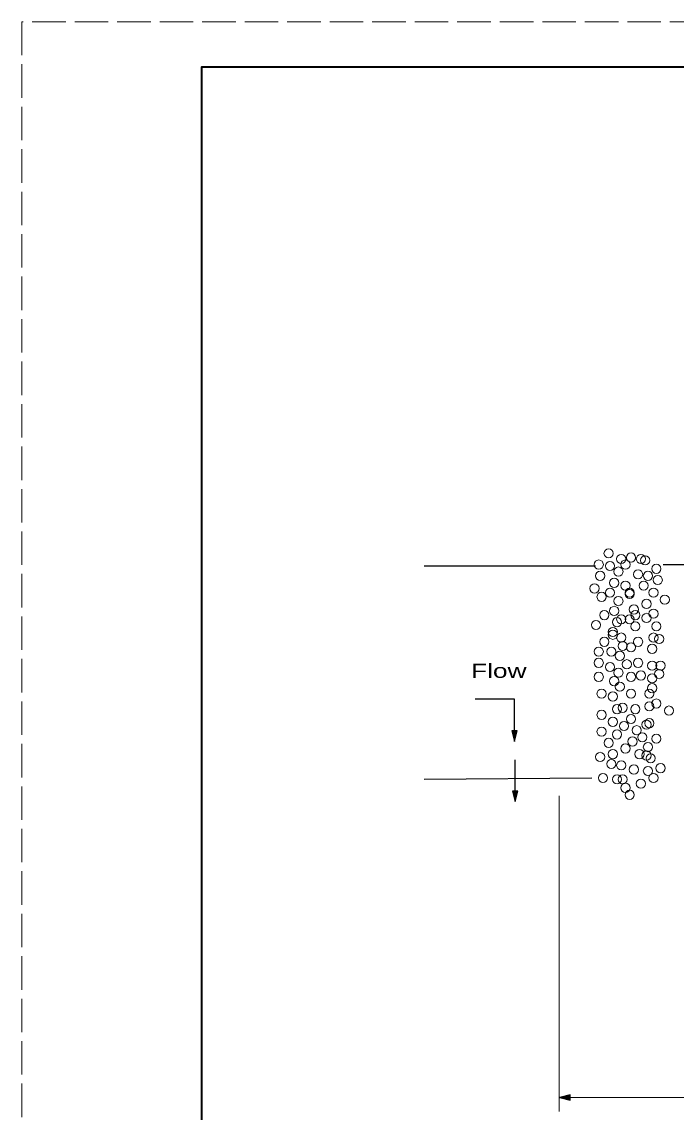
# Model space of a CAD drawing. Extents: x 1083.1 to 1117.1, y 719.4 to 741.4.
# Drawn here: x 1083.13 to 1090.39, y 729.24 to 741.35 of the extents above; entities that cross this region are included whole.
import ezdxf

# ---------------------------------------------------------------- set-up
doc = ezdxf.new("R2010")
doc.units = 0
doc.header["$LTSCALE"] = 0.062
doc.linetypes.add('LONG_DASHED', pattern=[7.5, 6, -1.5])
doc.layers.add('1', color=7, linetype='Continuous', lineweight=13)

msp = doc.modelspace()

# ---------------------------------------------------------------- hatches: boundary and pattern name
at = {"layer": '1'}
for points in [[(1088.56667, 733.4755), (1088.59608, 733.358), (1088.6255, 733.4755)], [(1088.57683, 732.80525), (1088.60625, 732.68775), (1088.63567, 732.80525)], [(1089.21717, 729.42983), (1089.09967, 729.4005), (1089.21717, 729.37117)]]:
    msp.add_hatch(color=256, dxfattribs=at).paths.add_polyline_path(points)

# ---------------------------------------------------------------- linework, layer by layer
at = {"layer": '1', "lineweight": 25}
for p, q in [((1085.12642, 740.85408), (1116.62642, 740.85408)), ((1087.59467, 735.3075), (1089.49675, 735.3075)), ((1090.24975, 735.32317), (1097.05567, 735.3075)), ((1087.59467, 732.93767), (1089.45433, 732.95158))]:
    msp.add_line(p, q, dxfattribs=at)
at = {"layer": '1', "lineweight": 40}
msp.add_line((1085.12642, 740.85408), (1116.62642, 740.85408), dxfattribs=at)
at = {"layer": '1'}
for p, q in [((1089.09142, 732.75375), (1089.09142, 729.2445)), ((1089.09142, 729.4005), (1093.66375, 729.4005))]:
    msp.add_line(p, q, dxfattribs=at)
at = {"layer": '1', "linetype": 'LONG_DASHED'}
msp.add_lwpolyline([(1083.12642, 719.35408), (1117.12642, 719.35408), (1117.12642, 741.35408), (1083.12642, 741.35408)], close=True, dxfattribs=at)
at = {"layer": '1', "lineweight": 25}
for points in [[(1116.62642, 719.85408), (1085.12642, 719.85408), (1085.12642, 740.85408)], [(1088.59608, 733.358), (1088.59608, 733.82517), (1088.15958, 733.82517)], [(1088.60625, 732.68775), (1088.60625, 732.901), (1088.60625, 733.151)]]:
    msp.add_lwpolyline(points, dxfattribs=at)
at = {"layer": '1', "lineweight": 40}
for points in [[(1116.62642, 719.85408), (1085.12642, 719.85408), (1085.12642, 740.85408), (1116.62642, 740.85408)], [(1116.62642, 719.85408), (1085.12642, 719.85408), (1085.12642, 740.85408)]]:
    msp.add_lwpolyline(points, dxfattribs=at)
at = {"layer": '1', "lineweight": 25}
for points in [[(1088.56667, 733.4755), (1088.59608, 733.358), (1088.6255, 733.4755)], [(1088.57683, 732.80525), (1088.60625, 732.68775), (1088.63567, 732.80525)], [(1089.21717, 729.42983), (1089.09967, 729.4005), (1089.21717, 729.37117)]]:
    msp.add_lwpolyline(points, close=True, dxfattribs=at)
at = {"layer": '1'}
for centre in [(1089.6421, 735.44728), (1089.78243, 735.38487), (1089.89168, 735.40053), (1090.00085, 735.38487), (1090.04764, 735.36932), (1089.53293, 735.32245), (1089.65768, 735.30687), (1089.75131, 735.24449), (1089.82931, 735.32249), (1090.17239, 735.27566), (1089.54851, 735.1977), (1089.70447, 735.11966), (1089.96964, 735.21332), (1090.07881, 735.19766), (1090.18797, 735.15091), (1089.4861, 735.05728), (1089.65768, 735.01045), (1089.82931, 735.08849), (1089.87606, 735.01049), (1089.87606, 734.99482), (1090.03206, 735.08849), (1090.14122, 735.01049), (1090.14122, 735.01049), (1089.5641, 734.96362), (1089.75131, 734.91682), (1090.06322, 734.88566), (1090.26593, 734.93245), (1089.59535, 734.76078), (1089.70447, 734.80766), (1089.92289, 734.82324), (1089.93847, 734.76082), (1090.14122, 734.77641), (1089.50176, 734.65162), (1089.73572, 734.68282), (1089.78247, 734.71399), (1089.87606, 734.71399), (1089.93847, 734.63599), (1090.06322, 734.72966), (1090.17239, 734.63599), (1089.68885, 734.57353), (1089.68889, 734.54241), (1089.78247, 734.51116), (1090.14122, 734.51116), (1090.2036, 734.49553), (1089.59531, 734.46441), (1089.79806, 734.41757), (1089.89164, 734.40199), (1089.96964, 734.46441), (1090.12564, 734.38641), (1089.53293, 734.35512), (1089.67326, 734.35512), (1089.76689, 734.30832), (1089.53293, 734.23028), (1089.65772, 734.18357), (1089.84489, 734.21474), (1089.96964, 734.23032), (1090.12564, 734.19916), (1090.21918, 734.19912), (1089.53293, 734.07428), (1089.70447, 734.02749), (1089.75131, 734.12116), (1089.89164, 734.07432), (1090.00081, 734.08991), (1090.12564, 734.05874), (1090.2036, 734.10553), (1089.5641, 733.88712), (1089.76689, 733.96507), (1089.89164, 733.88707), (1090.09439, 733.88707), (1090.12564, 733.94949), (1089.68889, 733.85591), (1090.17235, 733.77787), (1089.5641, 733.65303), (1089.73572, 733.71549), (1089.79806, 733.73107), (1089.93847, 733.71549), (1090.09439, 733.74666), (1090.31276, 733.69987), (1089.68889, 733.57507), (1089.81364, 733.52824), (1089.89164, 733.60624), (1090.06322, 733.54382), (1090.09439, 733.55949), (1089.5641, 733.46578), (1089.73572, 733.43466), (1089.95406, 733.48141), (1090.01647, 733.40341), (1089.64214, 733.34099), (1089.90722, 733.35666), (1090.07881, 733.29424), (1090.17235, 733.38778), (1089.54851, 733.18495), (1089.68889, 733.21624), (1089.82931, 733.27857), (1089.98522, 733.21624), (1090.06322, 733.20057), (1090.10997, 733.16941), (1089.67331, 733.10699), (1089.78247, 733.09141), (1089.92289, 733.04457), (1090.21918, 733.06012), (1089.57972, 732.95099), (1089.73572, 732.93532), (1089.79806, 732.93532), (1090.07881, 733.02899), (1090.14122, 732.95099), (1089.82931, 732.84174), (1090.00081, 732.88857), (1089.87606, 732.76374)]:
    msp.add_circle(centre, 0.05102, dxfattribs=at)

# ---------------------------------------------------------------- texts
at = {"layer": '1', "width": 1.4}
msp.add_text('Flow', height=0.156, dxfattribs=at).set_placement((1088.1145, 734.06383))

doc.saveas('drawing.dxf')
